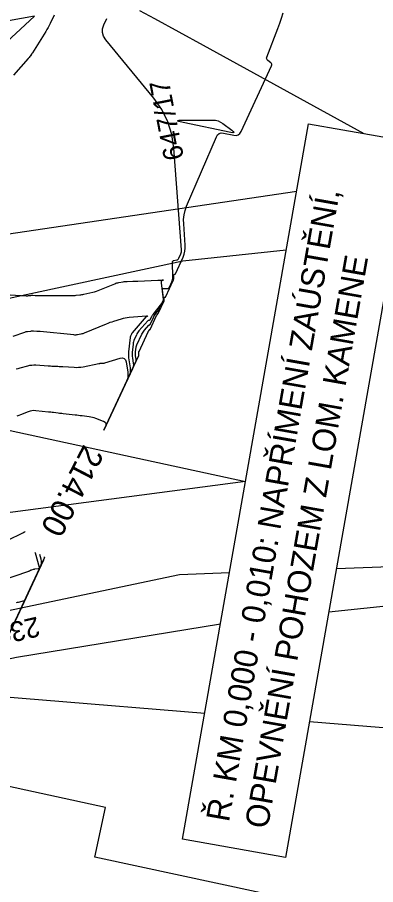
# Model space of a CAD drawing. Extents: x -534481 to -534262, y -1190577 to -1190138.
# Drawn here: x -534390.37 to -534375, y -1190542.27 to -1190505.1 of the extents above; entities that cross this region are included whole.
import ezdxf

# ---------------------------------------------------------------- set-up
doc = ezdxf.new("R2010")
doc.units = 0
for name, color, linetype in [('Definiční body', 7, 'Continuous'), ('Polygon budovy', 7, 'Continuous'), ('Polygon parcely', 7, 'Continuous'), ('Vrstva 17', 7, 'Continuous'), ('Vrstva 18', 7, 'Continuous'), ('Vrstva 19', 7, 'Continuous'), ('Vrstva 31', 7, 'Continuous')]:
    doc.layers.add(name, color=color, linetype=linetype)

msp = doc.modelspace()

# ---------------------------------------------------------------- linework, layer by layer
at = {"layer": 'Definiční body'}
for p, q in [((-534389.63, -1190505.06), (-534401.56, -1190515.98)), ((-534401.56, -1190515.98), (-534378.386, -1190512.549))]:
    msp.add_line(p, q, dxfattribs=at)
for points in [[(-534385.13, -1190504.81), (-534384.49, -1190505.16), (-534382.4, -1190506.3), (-534375.507, -1190510.084)], [(-534389.63, -1190505.06), (-534396.5, -1190506.28), (-534398.08, -1190506.56), (-534402.44, -1190507.34), (-534402.95, -1190507.61)], [(-534378.833, -1190515.085), (-534383.27, -1190515.56), (-534409.16, -1190521.11), (-534410.57, -1190521.41), (-534422.34, -1190523.93)], [(-534376.683, -1190528.726), (-534346.53, -1190527.59)], [(-534424.26, -1190537.56), (-534383.41, -1190528.98), (-534381.269, -1190528.899)], [(-534363.09, -1190529.14), (-534377.014, -1190530.603)], [(-534381.658, -1190531.109), (-534390.4, -1190532.54), (-534396.26, -1190533.8)], [(-534382.333, -1190534.934), (-534396.26, -1190533.8)], [(-534362.76, -1190542.27), (-534370.46, -1190535.9), (-534377.842, -1190535.299)]]:
    msp.add_lwpolyline(points, dxfattribs=at)
at = {"layer": 'Polygon parcely'}
msp.add_lwpolyline([(-534400.19, -1190541.92), (-534394.59, -1190543.13), (-534394.89, -1190544.51), (-534390.54, -1190545.47), (-534390.82, -1190546.76), (-534389.15, -1190547.11), (-534390.54, -1190553.66), (-534381.04, -1190555.72), (-534378.2, -1190543), (-534387.05, -1190541.1), (-534386.59, -1190538.96), (-534391.46, -1190537.91), (-534391.92, -1190540.05), (-534399.41, -1190538.44)], close=True, dxfattribs=at)
at = {"layer": 'Vrstva 18'}
for points in [[(-534388.782, -1190505.006), (-534388.96, -1190505.368), (-534389.004, -1190505.454), (-534389.05, -1190505.54), (-534389.098, -1190505.624), (-534389.149, -1190505.707), (-534389.725, -1190506.624), (-534389.734, -1190506.639), (-534389.743, -1190506.653), (-534389.753, -1190506.668), (-534389.762, -1190506.682), (-534389.806, -1190506.747), (-534389.813, -1190506.758), (-534389.82, -1190506.768), (-534389.828, -1190506.777), (-534389.835, -1190506.787), (-534389.866, -1190506.825), (-534389.874, -1190506.835), (-534389.882, -1190506.844), (-534389.89, -1190506.854), (-534389.898, -1190506.863), (-534390.536, -1190507.586)], [(-534386.653, -1190522.8), (-534385.274, -1190519.839), (-534385.161, -1190519.596), (-534385.158, -1190519.588), (-534385.156, -1190519.581), (-534385.156, -1190519.573), (-534385.156, -1190519.565), (-534385.162, -1190519.533), (-534385.163, -1190519.525), (-534385.163, -1190519.517), (-534385.163, -1190519.509), (-534385.163, -1190519.501), (-534385.158, -1190519.459), (-534385.157, -1190519.449), (-534385.155, -1190519.44), (-534385.152, -1190519.431), (-534385.148, -1190519.422), (-534384.759, -1190518.579), (-534384.753, -1190518.568), (-534384.747, -1190518.557), (-534384.74, -1190518.548), (-534384.732, -1190518.538), (-534384.686, -1190518.485), (-534384.683, -1190518.483), (-534384.675, -1190518.481), (-534384.673, -1190518.48), (-534384.673, -1190518.479), (-534384.399, -1190517.889), (-534384.394, -1190517.878), (-534384.387, -1190517.867), (-534384.38, -1190517.857), (-534384.373, -1190517.847), (-534384.342, -1190517.807), (-534384.334, -1190517.797), (-534384.328, -1190517.787), (-534384.321, -1190517.776), (-534384.316, -1190517.765), (-534384.075, -1190517.248), (-534384.07, -1190517.233), (-534384.066, -1190517.218), (-534384.065, -1190517.203), (-534384.066, -1190517.187), (-534384.076, -1190517.109), (-534384.076, -1190517.102), (-534384.073, -1190517.096), (-534384.068, -1190517.093), (-534384.06, -1190517.091), (-534384.025, -1190517.091), (-534384.017, -1190517.09), (-534384.01, -1190517.086), (-534384.004, -1190517.081), (-534384, -1190517.074), (-534383.681, -1190516.389), (-534383.671, -1190516.364), (-534383.664, -1190516.338), (-534383.66, -1190516.312), (-534383.659, -1190516.285), (-534383.662, -1190516.139), (-534383.661, -1190516.132), (-534383.658, -1190516.126), (-534383.653, -1190516.122), (-534383.646, -1190516.12), (-534383.614, -1190516.113), (-534383.606, -1190516.111), (-534383.6, -1190516.107), (-534383.595, -1190516.102), (-534383.591, -1190516.095), (-534383.258, -1190515.378), (-534383.21, -1190515.254), (-534383.179, -1190515.127), (-534383.164, -1190514.998), (-534383.165, -1190514.865), (-534383.233, -1190513.957), (-534383.236, -1190513.762), (-534383.216, -1190513.572), (-534383.173, -1190513.386), (-534383.107, -1190513.203), (-534381.832, -1190510.227), (-534381.78, -1190510.14), (-534381.711, -1190510.084), (-534381.626, -1190510.06), (-534381.525, -1190510.067), (-534381.086, -1190510.158), (-534380.984, -1190510.166), (-534380.898, -1190510.142), (-534380.827, -1190510.087), (-534380.772, -1190510.001), (-534379.465, -1190507.177), (-534379.454, -1190507.14), (-534379.455, -1190507.106), (-534379.47, -1190507.076), (-534379.497, -1190507.049), (-534379.631, -1190506.947), (-534379.659, -1190506.92), (-534379.674, -1190506.889), (-534379.677, -1190506.855), (-534379.668, -1190506.818), (-534379.196, -1190505.58), (-534379.116, -1190505.36), (-534379.041, -1190505.138), (-534378.973, -1190504.913)], [(-534391.592, -1190516.943), (-534389.984, -1190517.034), (-534389.96, -1190517.035), (-534389.935, -1190517.035), (-534389.911, -1190517.033), (-534389.887, -1190517.031), (-534389.787, -1190517.019), (-534389.765, -1190517.017), (-534389.743, -1190517.015), (-534389.721, -1190517.015), (-534389.699, -1190517.016), (-534389.61, -1190517.02), (-534389.588, -1190517.021), (-534389.565, -1190517.022), (-534389.543, -1190517.022), (-534389.521, -1190517.022), (-534388.006, -1190517.026), (-534387.966, -1190517.025), (-534387.925, -1190517.024), (-534387.884, -1190517.02), (-534387.844, -1190517.016), (-534387.683, -1190516.996), (-534387.642, -1190516.99), (-534387.602, -1190516.984), (-534387.562, -1190516.976), (-534387.523, -1190516.968), (-534387.133, -1190516.88), (-534387.055, -1190516.861), (-534386.979, -1190516.838), (-534386.903, -1190516.812), (-534386.829, -1190516.783), (-534386.19, -1190516.518), (-534386.147, -1190516.501), (-534386.104, -1190516.487), (-534386.06, -1190516.476), (-534386.015, -1190516.467), (-534385.834, -1190516.437), (-534385.788, -1190516.43), (-534385.743, -1190516.425), (-534385.697, -1190516.421), (-534385.651, -1190516.42), (-534385.419, -1190516.415), (-534385.365, -1190516.413), (-534385.311, -1190516.412), (-534385.257, -1190516.41), (-534385.203, -1190516.408), (-534384.341, -1190516.371), (-534384.281, -1190516.369), (-534384.221, -1190516.367), (-534384.162, -1190516.365), (-534384.102, -1190516.364), (-534384.153, -1190516.372), (-534384.188, -1190516.395), (-534384.205, -1190516.433), (-534384.206, -1190516.485), (-534384.114, -1190517.192), (-534384.113, -1190517.207), (-534384.115, -1190517.222), (-534384.118, -1190517.237), (-534384.124, -1190517.251), (-534384.15, -1190517.308), (-534384.157, -1190517.322), (-534384.165, -1190517.336), (-534384.173, -1190517.349), (-534384.183, -1190517.361), (-534384.559, -1190517.838), (-534384.576, -1190517.861), (-534384.591, -1190517.884), (-534384.605, -1190517.909), (-534384.618, -1190517.934), (-534384.681, -1190518.07), (-534384.686, -1190518.078), (-534384.692, -1190518.084), (-534384.699, -1190518.088), (-534384.708, -1190518.09), (-534384.746, -1190518.096), (-534384.755, -1190518.098), (-534384.763, -1190518.101), (-534384.771, -1190518.106), (-534384.777, -1190518.113), (-534385.152, -1190518.546), (-534385.184, -1190518.586), (-534385.214, -1190518.628), (-534385.24, -1190518.673), (-534385.264, -1190518.719), (-534385.351, -1190518.908), (-534385.371, -1190518.956), (-534385.387, -1190519.005), (-534385.398, -1190519.055), (-534385.405, -1190519.106), (-534385.441, -1190519.462), (-534385.446, -1190519.522), (-534385.446, -1190519.582), (-534385.442, -1190519.641), (-534385.434, -1190519.701), (-534385.396, -1190519.939), (-534385.39, -1190519.998), (-534385.394, -1190520.056), (-534385.406, -1190520.113), (-534385.427, -1190520.168), (-534386.653, -1190522.8)], [(-534390.417, -1190520.171), (-534390.333, -1190520.148), (-534390.248, -1190520.126), (-534389.912, -1190520.036), (-534389.827, -1190520.017), (-534389.742, -1190520.005), (-534389.656, -1190520), (-534389.569, -1190520.003), (-534389.048, -1190520.037), (-534388.996, -1190520.041), (-534388.943, -1190520.044), (-534388.891, -1190520.047), (-534388.838, -1190520.05), (-534388.628, -1190520.06), (-534388.576, -1190520.062), (-534388.523, -1190520.065), (-534388.471, -1190520.068), (-534388.418, -1190520.071), (-534387.938, -1190520.102), (-534387.841, -1190520.105), (-534387.744, -1190520.102), (-534387.648, -1190520.092), (-534387.551, -1190520.076), (-534386.871, -1190519.94), (-534386.851, -1190519.936), (-534386.83, -1190519.933), (-534386.809, -1190519.931), (-534386.788, -1190519.93), (-534386.704, -1190519.927), (-534386.684, -1190519.925), (-534386.663, -1190519.922), (-534386.643, -1190519.918), (-534386.622, -1190519.913), (-534385.959, -1190519.712), (-534385.862, -1190519.697), (-534385.788, -1190519.718), (-534385.736, -1190519.776), (-534385.707, -1190519.869), (-534385.635, -1190520.313), (-534385.625, -1190520.423), (-534385.631, -1190520.531), (-534385.654, -1190520.637), (-534385.694, -1190520.74), (-534386.653, -1190522.8)], [(-534389.613, -1190528.024), (-534389.606, -1190528.056), (-534389.43, -1190528.662), (-534389.426, -1190528.689), (-534389.432, -1190528.71), (-534389.448, -1190528.724), (-534389.474, -1190528.733), (-534389.629, -1190528.758), (-534389.645, -1190528.761), (-534389.661, -1190528.764), (-534389.677, -1190528.768), (-534389.693, -1190528.772), (-534389.766, -1190528.793), (-534389.777, -1190528.797), (-534389.788, -1190528.801), (-534389.798, -1190528.805), (-534389.808, -1190528.811), (-534389.849, -1190528.833), (-534389.859, -1190528.839), (-534389.87, -1190528.844), (-534389.88, -1190528.848), (-534389.891, -1190528.852), (-534391.16, -1190529.276)], [(-534391.016, -1190532.165), (-534389.189, -1190528.244)], [(-534389.218, -1190528.229), (-534389.217, -1190528.26), (-534389.227, -1190528.313), (-534389.246, -1190528.366), (-534390.653, -1190531.386)]]:
    msp.add_lwpolyline(points, dxfattribs=at)
at = {"layer": 'Vrstva 19'}
for points in [[(-534386.653, -1190522.8), (-534385.856, -1190521.088), (-534385.294, -1190519.882), (-534385.282, -1190519.85), (-534385.275, -1190519.818), (-534385.273, -1190519.786), (-534385.276, -1190519.752), (-534385.298, -1190519.617), (-534385.302, -1190519.583), (-534385.305, -1190519.549), (-534385.304, -1190519.515), (-534385.302, -1190519.481), (-534385.284, -1190519.303), (-534385.278, -1190519.263), (-534385.269, -1190519.223), (-534385.257, -1190519.184), (-534385.241, -1190519.146), (-534385.026, -1190518.68), (-534385.004, -1190518.636), (-534384.978, -1190518.594), (-534384.95, -1190518.554), (-534384.919, -1190518.515), (-534384.732, -1190518.299), (-534384.728, -1190518.295), (-534384.724, -1190518.292), (-534384.719, -1190518.29), (-534384.714, -1190518.289), (-534384.692, -1190518.286), (-534384.687, -1190518.285), (-534384.683, -1190518.282), (-534384.68, -1190518.279), (-534384.677, -1190518.275), (-534384.533, -1190517.965), (-534384.511, -1190517.92), (-534384.486, -1190517.878), (-534384.459, -1190517.836), (-534384.43, -1190517.796), (-534384.303, -1190517.636), (-534384.275, -1190517.598), (-534384.249, -1190517.559), (-534384.226, -1190517.519), (-534384.205, -1190517.477), (-534384.126, -1190517.306), (-534384.109, -1190517.263), (-534384.099, -1190517.219), (-534384.095, -1190517.174), (-534384.098, -1190517.128), (-534384.141, -1190516.797), (-534384.141, -1190516.767), (-534384.13, -1190516.746), (-534384.111, -1190516.732), (-534384.081, -1190516.728), (-534383.944, -1190516.725), (-534383.912, -1190516.72), (-534383.885, -1190516.708), (-534383.863, -1190516.688), (-534383.846, -1190516.661), (-534383.744, -1190516.442), (-534383.725, -1190516.394), (-534383.712, -1190516.345), (-534383.704, -1190516.296), (-534383.702, -1190516.244), (-534383.715, -1190515.597), (-534383.712, -1190515.569), (-534383.701, -1190515.548), (-534383.682, -1190515.532), (-534383.656, -1190515.523), (-534383.534, -1190515.499), (-534383.506, -1190515.49), (-534383.482, -1190515.476), (-534383.463, -1190515.456), (-534383.448, -1190515.431), (-534383.361, -1190515.243), (-534383.345, -1190515.202), (-534383.334, -1190515.16), (-534383.329, -1190515.116), (-534383.33, -1190515.072), (-534383.654, -1190510.714), (-534383.741, -1190510.128), (-534383.913, -1190509.577), (-534384.169, -1190509.059), (-534384.511, -1190508.575), (-534386.572, -1190506.067), (-534386.668, -1190505.918), (-534386.714, -1190505.761), (-534386.711, -1190505.598), (-534386.659, -1190505.429), (-534386.535, -1190505.149)], [(-534386.653, -1190522.8), (-534385.56, -1190520.454), (-534385.53, -1190520.375), (-534385.513, -1190520.294), (-534385.508, -1190520.211), (-534385.515, -1190520.126), (-534385.571, -1190519.785), (-534385.582, -1190519.699), (-534385.587, -1190519.614), (-534385.587, -1190519.528), (-534385.581, -1190519.442), (-534385.518, -1190518.819), (-534385.515, -1190518.802), (-534385.511, -1190518.785), (-534385.506, -1190518.769), (-534385.5, -1190518.753), (-534385.47, -1190518.69), (-534385.463, -1190518.674), (-534385.454, -1190518.659), (-534385.444, -1190518.645), (-534385.433, -1190518.632), (-534384.823, -1190517.927), (-534384.813, -1190517.918), (-534384.803, -1190517.91), (-534384.791, -1190517.905), (-534384.778, -1190517.902), (-534384.791, -1190517.904), (-534384.805, -1190517.906), (-534384.819, -1190517.907), (-534384.832, -1190517.909), (-534385.572, -1190517.975), (-534385.657, -1190517.985), (-534385.742, -1190517.998), (-534385.825, -1190518.016), (-534385.908, -1190518.038), (-534386.239, -1190518.135), (-534386.321, -1190518.161), (-534386.402, -1190518.188), (-534386.483, -1190518.218), (-534386.563, -1190518.25), (-534387.495, -1190518.637), (-534387.53, -1190518.651), (-534387.566, -1190518.663), (-534387.603, -1190518.673), (-534387.64, -1190518.681), (-534387.79, -1190518.709), (-534387.827, -1190518.715), (-534387.865, -1190518.718), (-534387.902, -1190518.718), (-534387.94, -1190518.716), (-534389.396, -1190518.573), (-534389.43, -1190518.57), (-534389.465, -1190518.567), (-534389.5, -1190518.565), (-534389.535, -1190518.563), (-534389.678, -1190518.556), (-534389.71, -1190518.555), (-534389.743, -1190518.556), (-534389.776, -1190518.558), (-534389.808, -1190518.561), (-534389.938, -1190518.577), (-534389.97, -1190518.581), (-534390.002, -1190518.588), (-534390.034, -1190518.596), (-534390.065, -1190518.606), (-534390.567, -1190518.78)], [(-534386.653, -1190522.8), (-534386.579, -1190522.641), (-534386.558, -1190522.57), (-534386.565, -1190522.511), (-534386.601, -1190522.463), (-534386.666, -1190522.426), (-534386.998, -1190522.296), (-534387.069, -1190522.271), (-534387.142, -1190522.25), (-534387.215, -1190522.234), (-534387.29, -1190522.222), (-534387.592, -1190522.184), (-534387.668, -1190522.175), (-534387.743, -1190522.166), (-534387.819, -1190522.157), (-534387.894, -1190522.149), (-534388.401, -1190522.093), (-534388.454, -1190522.087), (-534388.506, -1190522.081), (-534388.559, -1190522.075), (-534388.612, -1190522.068), (-534388.823, -1190522.043), (-534388.876, -1190522.036), (-534388.928, -1190522.03), (-534388.981, -1190522.024), (-534389.034, -1190522.018), (-534389.57, -1190521.961), (-534389.656, -1190521.957), (-534389.74, -1190521.963), (-534389.823, -1190521.979), (-534389.905, -1190522.006), (-534390.228, -1190522.134), (-534390.309, -1190522.164), (-534390.392, -1190522.192)], [(-534390.777, -1190527.517), (-534390.131, -1190527.193), (-534390.092, -1190527.174), (-534390.053, -1190527.154), (-534390.029, -1190527.142)], [(-534390.834, -1190531.775), (-534389.814, -1190529.586), (-534389.189, -1190528.244)], [(-534390.402, -1190530.184), (-534390.358, -1190530.174), (-534390.314, -1190530.163), (-534390.061, -1190530.097), (-534390.056, -1190530.096), (-534390.053, -1190530.093), (-534390.05, -1190530.09), (-534390.047, -1190530.086), (-534390.031, -1190530.05), (-534389.376, -1190528.644), (-534389.348, -1190528.567), (-534389.334, -1190528.49), (-534389.336, -1190528.41), (-534389.352, -1190528.33), (-534389.41, -1190528.129)]]:
    msp.add_lwpolyline(points, dxfattribs=at)
msp.add_lwpolyline([(-534381.105, -1190510.001), (-534381.089, -1190510.037), (-534381.127, -1190510.048), (-534381.217, -1190510.036), (-534383.254, -1190509.611), (-534383.437, -1190509.566), (-534383.496, -1190509.534), (-534383.431, -1190509.515), (-534383.243, -1190509.509), (-534381.981, -1190509.509), (-534381.865, -1190509.518), (-534381.755, -1190509.545), (-534381.651, -1190509.59), (-534381.553, -1190509.653), (-534381.173, -1190509.941)], close=True, dxfattribs=at)
at = {"layer": 'Vrstva 31'}
msp.add_line((-534405.492, -1190519.605), (-534380.58, -1190524.995), dxfattribs=at)
msp.add_lwpolyline([(-534383.283, -1190540.324), (-534377.877, -1190509.666), (-534373.459, -1190510.445), (-534378.865, -1190541.103)], close=True, dxfattribs=at)
msp.add_lwpolyline([(-534380.58, -1190524.995), (-534412.047, -1190529.146), (-534410.245, -1190529.642)], dxfattribs=at)

# ---------------------------------------------------------------- texts
at = {"layer": 'Polygon budovy'}
for s, rotation, p in [('647/17', 101, (-534383.217, -1190511.145)), ('2302/512', 193, (-534389.518, -1190530.781))]:
    msp.add_text(s, height=0.85, rotation=rotation, dxfattribs=at).set_placement(p)
at = {"layer": 'Vrstva 17'}
msp.add_text('214.00', height=1, rotation=242.6092, dxfattribs=at).set_placement((-534387.51, -1190523.367))
at = {"layer": 'Vrstva 31'}
for s, p in [('Ř. KM 0,000 - 0,010: NAPŘÍMENÍ ZAÚSTĚNÍ, ', (-534381.294, -1190539.622)), ('OPEVNĚNÍ POHOZEM Z LOM. KAMENE', (-534379.632, -1190539.915))]:
    msp.add_text(s, height=1, rotation=80.0205, dxfattribs=at).set_placement(p)

doc.saveas('drawing.dxf')
